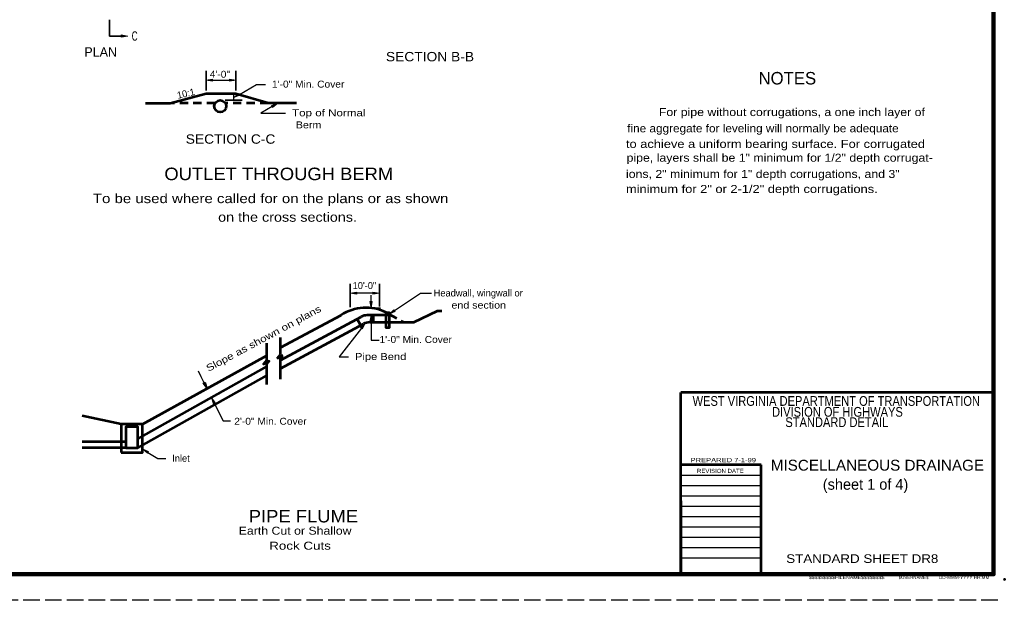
# Model space of a CAD drawing. Extents: x 36.1 to 71.5, y 0.2 to 22.2.
# Drawn here: x 52.56 to 71.48, y 0.21 to 11.37 of the extents above; entities that cross this region are included whole.
import ezdxf
from ezdxf.enums import TextEntityAlignment as Align

# ---------------------------------------------------------------- set-up
doc = ezdxf.new("R2010")
doc.units = 0
doc.header["$LTSCALE"] = 0.053
doc.header["$PDMODE"] = 32
doc.header["$PDSIZE"] = 0.0265
doc.linetypes.add('LONG_DASHED', pattern=[7.5, 6, -1.5])
doc.linetypes.add('MEDIUM_DASHED', pattern=[4.5, 3, -1.5])
for name, color, linetype, lineweight in [('1', 7, 'Continuous', 35), ('2', 7, 'MEDIUM_DASHED', 53), ('3', 7, 'Continuous', 25), ('5', 7, 'Continuous', 35), ('6', 7, 'Continuous', 13)]:
    doc.layers.add(name, color=color, linetype=linetype, lineweight=lineweight)

msp = doc.modelspace()

# ---------------------------------------------------------------- hatches: boundary and pattern name
at = {"layer": '1'}
for points in [[(56.26125, 10.18267), (56.26125, 10.22433), (56.13625, 10.2035), (56.13625, 10.2035)], [(56.58425, 10.18267), (56.58425, 10.22433), (56.70925, 10.2035), (56.70925, 10.2035)], [(59.02983, 6.09325), (59.02983, 6.13492), (58.90483, 6.11408), (58.90483, 6.11408)], [(59.34017, 6.09325), (59.34017, 6.13492), (59.46517, 6.11408), (59.46517, 6.11408)], [(59.3235, 5.95208), (59.28183, 5.95208), (59.30267, 5.82708), (59.30267, 5.82708)], [(59.3235, 5.5635), (59.28183, 5.5635), (59.30267, 5.6885), (59.30267, 5.6885)], [(56.08108, 4.38325), (56.1185, 4.40158), (56.15483, 4.28017), (56.15483, 4.28017)], [(56.276, 3.98592), (56.31342, 4.00433), (56.23967, 4.10733), (56.23967, 4.10733)]]:
    msp.add_hatch(color=256, dxfattribs=at).paths.add_polyline_path(points)
at = {"layer": '3'}
for points in [[(56.7855, 9.913), (56.76458, 9.949), (56.66708, 9.86792), (56.66708, 9.86792)], [(57.393, 9.71542), (57.41408, 9.6795), (57.51158, 9.76042), (57.51158, 9.76042)], [(59.76592, 5.75983), (59.74267, 5.79433), (59.65067, 5.70725), (59.65067, 5.70725)], [(59.10392, 5.45417), (59.13675, 5.42858), (59.19708, 5.54), (59.19708, 5.54)], [(55.00867, 3.03767), (55.03117, 3.07275), (54.91475, 3.12267), (54.91475, 3.12267)]]:
    msp.add_hatch(color=256, dxfattribs=at).paths.add_polyline_path(points)
at = {"layer": '5'}
msp.add_hatch(color=256, dxfattribs=at).paths.add_polyline_path([(54.50808, 11.07258), (54.50808, 11.03092), (54.63308, 11.05175), (54.63308, 11.05175)])

# ---------------------------------------------------------------- linework, layer by layer
at = {"layer": '1', "lineweight": 158}
msp.add_line((71.25383, 21.71317), (71.25383, 0.71317), dxfattribs=at)
at = {"layer": '1'}
for p, q in [((56.13625, 10.0065), (56.13625, 10.3835)), ((56.70925, 10.0065), (56.70925, 10.3835)), ((58.90483, 5.84108), (58.90483, 6.29408)), ((59.46517, 5.85575), (59.46517, 6.29408)), ((59.36075, 5.82708), (59.48267, 5.82708))]:
    msp.add_line(p, q, dxfattribs=at)
at = {"layer": '1', "lineweight": 25}
for p, q in [((56.26125, 10.2035), (56.58425, 10.2035)), ((59.34017, 6.11408), (59.02983, 6.11408)), ((59.30267, 5.95208), (59.30267, 6.07708)), ((59.30267, 5.5635), (59.30267, 5.4385)), ((59.30267, 5.4385), (59.30267, 5.3135)), ((56.04475, 4.50458), (55.98967, 4.61683)), ((56.09983, 4.39242), (56.04475, 4.50458)), ((56.19158, 4.29817), (56.31642, 4.35942)), ((56.27633, 4.12533), (56.40125, 4.18658)), ((56.29467, 3.99508), (56.34975, 3.88292)), ((66.79175, 2.61217), (65.25383, 2.61217)), ((66.79175, 2.41317), (65.25383, 2.41317)), ((66.79175, 2.21417), (65.25383, 2.21417)), ((66.79175, 2.01517), (65.25383, 2.01517)), ((66.79175, 1.81617), (65.25383, 1.81617)), ((66.79175, 1.61717), (65.25383, 1.61717)), ((66.79175, 1.41817), (65.25383, 1.41817)), ((66.79175, 1.21917), (65.25383, 1.21917)), ((66.79175, 1.02017), (65.25383, 1.02017))]:
    msp.add_line(p, q, dxfattribs=at)
at = {"layer": '1', "lineweight": 53}
for p, q in [((57.56325, 5.071), (58.72717, 5.69033)), ((59.65067, 5.6885), (59.23025, 5.6885)), ((59.35117, 5.55325), (59.35117, 5.6885)), ((57.56325, 4.82817), (59.11217, 5.65875)), ((57.56325, 4.66542), (59.159, 5.52342)), ((59.10525, 5.4945), (59.03858, 5.61933)), ((57.56325, 4.93717), (57.56325, 5.26242)), ((57.498, 4.85725), (57.56325, 4.93717)), ((54.91475, 3.59625), (57.30217, 4.91525)), ((57.60675, 4.91433), (57.498, 4.85725)), ((57.56325, 4.85725), (57.60675, 4.91433)), ((57.56325, 4.46358), (57.56325, 4.85725)), ((54.82767, 3.31667), (57.30217, 4.70475)), ((54.82767, 3.13975), (57.30217, 4.52792)), ((71.25383, 4.203), (65.25383, 4.203)), ((65.25383, 0.71317), (65.25383, 4.203)), ((54.50683, 3.59625), (53.75633, 3.756)), ((54.59383, 3.25392), (53.75633, 3.25392)), ((54.59383, 3.13975), (53.75633, 3.13975)), ((71.25383, 0.71317), (71.25383, 3.21217)), ((66.79175, 2.81217), (65.25383, 2.81217)), ((66.79175, 0.71317), (66.79175, 2.81217)), ((65.25383, 2.12317), (65.25383, 0.71317)), ((71.25383, 0.71317), (65.25383, 0.71317))]:
    msp.add_line(p, q, dxfattribs=at)
at = {"layer": '1', "lineweight": 13}
msp.add_line((59.36517, 5.6885), (59.48267, 5.6885), dxfattribs=at)
at = {"layer": '1', "linetype": 'LONG_DASHED', "lineweight": 25}
msp.add_line((71.33717, 0.21317), (36.13717, 0.21317), dxfattribs=at)
at = {"layer": '1', "lineweight": 158}
msp.add_lwpolyline([(71.25383, 21.71317), (71.25383, 0.71317), (38.75383, 0.71317)], dxfattribs=at)
at = {"layer": '1', "lineweight": 13}
for points in [[(56.26125, 10.18267), (56.26125, 10.22433), (56.13625, 10.2035), (56.13625, 10.2035)], [(56.58425, 10.18267), (56.58425, 10.22433), (56.70925, 10.2035), (56.70925, 10.2035)], [(59.02983, 6.09325), (59.02983, 6.13492), (58.90483, 6.11408), (58.90483, 6.11408)], [(59.34017, 6.09325), (59.34017, 6.13492), (59.46517, 6.11408), (59.46517, 6.11408)], [(59.3235, 5.95208), (59.28183, 5.95208), (59.30267, 5.82708), (59.30267, 5.82708)], [(59.3235, 5.5635), (59.28183, 5.5635), (59.30267, 5.6885), (59.30267, 5.6885)]]:
    msp.add_lwpolyline(points, close=True, dxfattribs=at)
at = {"layer": '1', "lineweight": 53}
for points in [[(57.8735, 9.76042), (57.33058, 9.76042), (56.70925, 9.944), (56.13625, 9.944), (55.4485, 9.75408), (54.972, 9.75408)], [(59.27742, 5.55325), (60.12533, 5.55325), (60.57675, 5.77575), (60.66375, 5.77575)], [(57.30217, 4.35517), (57.30217, 4.74883), (57.34567, 4.80592), (57.23692, 4.74883), (57.30217, 4.82875), (57.30217, 5.154)]]:
    msp.add_lwpolyline(points, dxfattribs=at)
for points in [[(59.59117, 5.744), (59.65067, 5.744), (59.65067, 5.44792), (59.59117, 5.44792)], [(54.50683, 3.05417), (54.91475, 3.05417), (54.91475, 3.59625), (54.50683, 3.59625)], [(54.59383, 3.13975), (54.82767, 3.13975), (54.82767, 3.54492), (54.59383, 3.54492)]]:
    msp.add_lwpolyline(points, close=True, dxfattribs=at)
at = {"layer": '1', "lineweight": 25}
for points in [[(56.08108, 4.38325), (56.1185, 4.40158), (56.15483, 4.28017), (56.15483, 4.28017)], [(56.276, 3.98592), (56.31342, 4.00433), (56.23967, 4.10733), (56.23967, 4.10733)]]:
    msp.add_lwpolyline(points, close=True, dxfattribs=at)
at = {"layer": '1', "lineweight": 53}
msp.add_circle((56.40767, 9.7035), 0.11461, dxfattribs=at)
for centre, radius, start, end in [((59.20692, 4.94775), 0.88408, 64.24028, 122.86358), ((59.23025, 5.4385), 0.25, 90, 118.20271), ((59.27742, 5.30325), 0.25, 90, 118.26544)]:
    msp.add_arc(centre, radius, start, end, dxfattribs=at)
at = {"layer": '1'}
for p in [(71.25383, 0.71317), (71.46683, 0.61317)]:
    msp.add_point(p, dxfattribs=at)
at = {"layer": '2'}
for p, q in [((56.30817, 9.76042), (55.47142, 9.76042)), ((57.33058, 9.76042), (56.50708, 9.76042)), ((59.65067, 5.71058), (59.93075, 5.55325))]:
    msp.add_line(p, q, dxfattribs=at)
at = {"layer": '3'}
msp.add_line((56.66708, 9.81858), (56.66708, 9.944), dxfattribs=at)
at = {"layer": '3', "lineweight": 35}
msp.add_line((56.50058, 9.81858), (56.83058, 9.81858), dxfattribs=at)
at = {"layer": '3'}
for points in [[(56.77508, 9.931), (57.10142, 10.12117), (57.27633, 10.12117)], [(57.40358, 9.6975), (57.18583, 9.57058), (57.66242, 9.57058)], [(59.75433, 5.77708), (60.25475, 6.11417), (60.46625, 6.11417)], [(59.12033, 5.44133), (58.69, 4.88875), (58.87075, 4.88875)], [(59.30267, 5.3135), (59.30267, 5.20775), (59.46133, 5.20775)], [(56.34975, 3.88292), (56.46467, 3.659), (56.60608, 3.659)], [(55.01992, 3.05517), (55.20842, 2.93433), (55.36067, 2.93433)]]:
    msp.add_lwpolyline(points, dxfattribs=at)
at = {"layer": '3', "lineweight": 13}
for points in [[(56.7855, 9.913), (56.76458, 9.949), (56.66708, 9.86792), (56.66708, 9.86792)], [(57.393, 9.71542), (57.41408, 9.6795), (57.51158, 9.76042), (57.51158, 9.76042)], [(59.76592, 5.75983), (59.74267, 5.79433), (59.65067, 5.70725), (59.65067, 5.70725)], [(59.10392, 5.45417), (59.13675, 5.42858), (59.19708, 5.54), (59.19708, 5.54)], [(55.00867, 3.03767), (55.03117, 3.07275), (54.91475, 3.12267), (54.91475, 3.12267)]]:
    msp.add_lwpolyline(points, close=True, dxfattribs=at)
at = {"layer": '5'}
for p, q in [((54.27892, 11.05175), (54.27892, 11.36)), ((54.50808, 11.05175), (54.27892, 11.05175))]:
    msp.add_line(p, q, dxfattribs=at)
at = {"layer": '5', "lineweight": 13}
msp.add_lwpolyline([(54.50808, 11.07258), (54.50808, 11.03092), (54.63308, 11.05175), (54.63308, 11.05175)], close=True, dxfattribs=at)
at = {"layer": '6'}
for p, q in [((56.70925, 10.2035), (56.70933, 10.2035)), ((56.13625, 9.944), (56.13633, 9.944)), ((56.70925, 9.944), (56.70933, 9.944)), ((58.90483, 6.11408), (58.90492, 6.11408)), ((58.90483, 5.77858), (58.90492, 5.77858)), ((59.29825, 5.82708), (59.29833, 5.82708)), ((59.30267, 5.6885), (59.30275, 5.6885)), ((59.30267, 5.6885), (59.30275, 5.6885)), ((59.46517, 5.79325), (59.46525, 5.79325))]:
    msp.add_line(p, q, dxfattribs=at)
at = {"layer": '6', "lineweight": 25}
for p, q in [((56.1355, 4.27067), (56.13558, 4.27067)), ((56.15483, 4.28017), (56.15492, 4.28017)), ((56.22025, 4.09783), (56.22033, 4.09783))]:
    msp.add_line(p, q, dxfattribs=at)

# ---------------------------------------------------------------- texts
at = {"layer": '1'}
for s, height, width, p in [('WEST VIRGINIA DEPARTMENT OF TRANSPORTATION', 0.1875, 0.85, (68.23558, 3.94808)), ('DIVISION OF HIGHWAYS', 0.1875, 0.85, (68.25746, 3.73917)), ('STANDARD DETAIL', 0.1875, 0.85, (68.24617, 3.541)), (' PREPARED 7-1-99', 0.08333, 1.3, (66.04613, 2.86492)), (' MISCELLANEOUS DRAINAGE ', 0.2083, 1.05, (69.02508, 2.70367)), ('STANDARD SHEET DR8       ', 0.1667, 1.15, (68.98396, 0.93025))]:
    msp.add_text(s, height=height, dxfattribs=dict(at, width=width)).set_placement(p, align=Align.CENTER)
for s, height, width, p in [('REVISION DATE', 0.079, 1.1, (65.56092, 2.6595)), ('$$$$$$$$$FILENAME$$$$$$$$', 0.06, 1.25, (67.70958, 0.62142)), ('$USERNAME$', 0.06, 1.05, (69.43367, 0.62142)), ('DD-MMM-YYYY HH:MM', 0.06, 1.1, (70.20725, 0.62142))]:
    msp.add_text(s, height=height, dxfattribs=dict(at, width=width)).set_placement(p)
msp.add_text('     (sheet 1 of 4)     ', height=0.2083, dxfattribs=at).set_placement((68.79704, 2.3365), align=Align.CENTER)
at = {"layer": '3'}
for s, height, p in [('PLAN', 0.18, (53.79825, 10.65525)), ('NOTES', 0.24, (66.74275, 10.12125)), ('10\'-0"', 0.133, (58.94992, 6.19183)), ('Headwall, wingwall or', 0.133, (60.50583, 6.04942)), ('Inlet', 0.133, (55.48567, 2.87433))]:
    msp.add_text(s, height=height, dxfattribs=at).set_placement(p)
for s, height, width, p in [('SECTION B-B', 0.18, 1.1, (59.58892, 10.56583)), ('4\'-0"', 0.133, 1.1, (56.20658, 10.25117)), ('1\'-0" Min. Cover', 0.133, 1.1, (57.40133, 10.06117)), ('Top of Normal', 0.133, 1.25, (57.78742, 9.51058)), ('For pipe without corrugations, a one inch layer of', 0.1536, 1.15, (64.82917, 9.5145)), ('Berm', 0.133, 1.15, (57.86008, 9.2785)), ('fine aggregate for leveling will normally be adequate', 0.1536, 1.1, (64.22125, 9.20258)), ('SECTION C-C', 0.18, 1.1, (55.74575, 8.98283)), ('to achieve a uniform bearing surface. For corrugated', 0.1536, 1.2, (64.19775, 8.9025)), ('pipe, layers shall be 1" minimum for 1/2" depth corrugat-', 0.1536, 1.15, (64.2095, 8.63767)), ('OUTLET THROUGH BERM', 0.24, 1.1, (55.3355, 8.2835)), ('ions, 2" minimum for 1" depth corrugations, and 3"', 0.1536, 1.15, (64.19775, 8.32567)), ('minimum for 2" or 2-1/2" depth corrugations.', 0.1536, 1.2, (64.19775, 8.03742)), ('To be used where called for on the plans or as shown', 0.1792, 1.2, (53.96308, 7.84208)), ('on the cross sections.', 0.1792, 1.15, (56.36767, 7.48425)), ('end section', 0.133, 1.15, (60.84783, 5.81675)), ('1\'-0" Min. Cover', 0.133, 1.1, (59.46575, 5.15692)), ('Pipe Bend', 0.133, 1.2, (58.99567, 4.82875)), ('2\'-0" Min. Cover', 0.133, 1.1, (56.67733, 3.58567)), ('PIPE FLUME', 0.24, 1.1, (56.9555, 1.70858)), ('Earth Cut or Shallow', 0.1536, 1.15, (56.76225, 1.47308)), ('Rock Cuts', 0.1536, 1.25, (57.34808, 1.18508))]:
    msp.add_text(s, height=height, dxfattribs=dict(at, width=width)).set_placement(p)
msp.add_text('10:1', height=0.133, rotation=12.658, dxfattribs=at).set_placement((55.59433, 9.84492))
at = {"layer": '3', "width": 1.25}
msp.add_text('Slope as shown on plans', height=0.133, rotation=28.232, dxfattribs=at).set_placement((56.1825, 4.60033))
at = {"layer": '5', "width": 0.65}
msp.add_text('C', height=0.18, dxfattribs=at).set_placement((54.70833, 10.96233))

doc.saveas('drawing.dxf')
